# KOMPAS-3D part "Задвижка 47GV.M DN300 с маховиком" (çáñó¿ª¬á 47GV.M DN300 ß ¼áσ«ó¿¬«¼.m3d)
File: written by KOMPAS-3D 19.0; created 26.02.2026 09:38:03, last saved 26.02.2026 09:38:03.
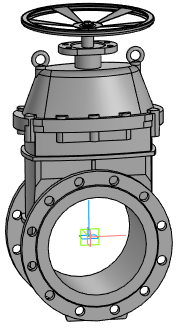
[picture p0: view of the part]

Document properties: Автор: Энергия; Полное имя файла: 47GV.M DN300\Задвижка 47GV.M DN300 с маховиком.a3d

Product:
- Part/product: Задвижка 47GV.M DN300 с маховиком
    Масса: 227.773
    source file: 47GV.M DN300\DR.47GVM.300.16.00.000 - Задвижка с обрезиненным клином DN300.spw
  - Component: Задвижка с обрезиненным клином DN300. Сборочный чертеж  | designation DR.47GVM.300.16.00.000СБ  | pos. 0  | Масса: 108.933; Раздел спецификации: Документация; Форматы листов документа: 2xA3; source file: ..\..\47GVM\DR.47GVM.300.16.00.000\DR.47GVM.300.16.00.000 СБ - Задвижка с обрезиненным клином DN300.cdw

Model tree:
1. Операция без истории:1

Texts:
  Точка начала. Х
  Точка начала. Y
  Точка начала. Z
